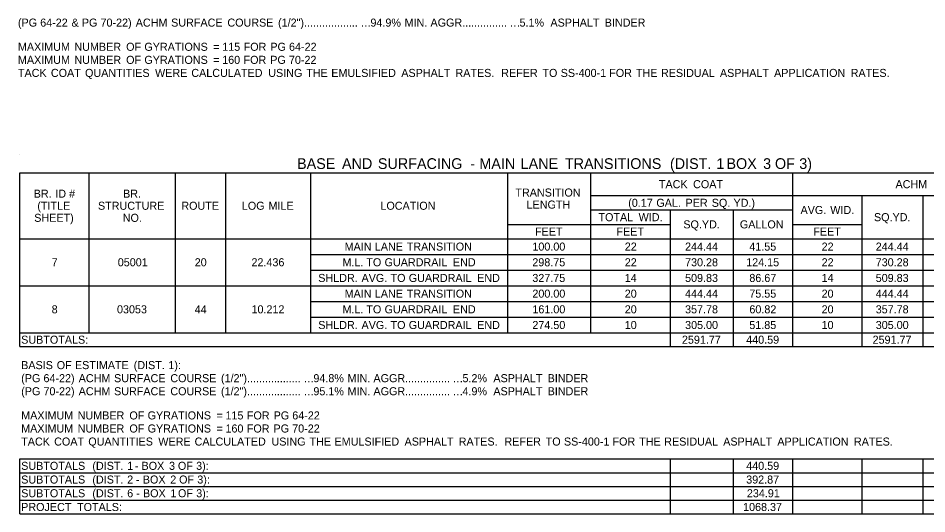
# Model space of a CAD drawing. Extents: x 542596 to 1930787, y -1948294 to 596640.
# Drawn here: x 548347 to 549024, y -1946912 to -1946543 of the extents above; entities that cross this region are included whole.
import ezdxf

# ---------------------------------------------------------------- set-up
doc = ezdxf.new("R2010")
doc.units = 0
doc.layers.add('Default', color=7, linetype='Continuous')

msp = doc.modelspace()

# ---------------------------------------------------------------- linework, layer by layer
at = {"layer": 'Default'}
for p, q in [((548348.01, -1946644.31), (548348.01, -1946644.31)), ((548348.01, -1946657.96), (549205.03, -1946657.96)), ((548348.01, -1946787.64), (548348.01, -1946657.96)), ((548399.68, -1946777.4), (548399.68, -1946657.96)), ((548464.03, -1946777.4), (548464.03, -1946657.96)), ((548501.57, -1946777.4), (548501.57, -1946657.96)), ((548564.95, -1946777.4), (548564.95, -1946657.96)), ((548711.68, -1946777.4), (548711.68, -1946657.96)), ((548773.6, -1946777.4), (548773.6, -1946657.96)), ((548924.23, -1946675.03), (548924.23, -1946657.96)), ((548924.23, -1946787.64), (548924.23, -1946657.96)), ((548773.6, -1946675.03), (549205.03, -1946675.03)), ((548975.91, -1946675.03), (549021.25, -1946675.03)), ((548975.91, -1946787.64), (548975.91, -1946675.03)), ((549021.25, -1946787.64), (549021.25, -1946675.03)), ((548773.6, -1946685.75), (548924.23, -1946685.75)), ((548833.07, -1946787.64), (548833.07, -1946685.75)), ((548879.87, -1946787.64), (548879.87, -1946685.75)), ((548711.68, -1946696.48), (548773.6, -1946696.48)), ((548711.68, -1946696.48), (548833.07, -1946696.48)), ((548833.07, -1946707.2), (548833.07, -1946696.48)), ((548924.23, -1946696.48), (548975.91, -1946696.48)), ((548924.23, -1946707.2), (548924.23, -1946696.48)), ((548975.91, -1946707.2), (548975.91, -1946696.48)), ((548348.01, -1946707.2), (549205.03, -1946707.2)), ((548833.07, -1946707.2), (548924.23, -1946707.2)), ((548924.23, -1946707.2), (549205.03, -1946707.2)), ((548564.95, -1946718.9), (549205.03, -1946718.9)), ((548924.23, -1946742.3), (548924.23, -1946718.9)), ((548975.91, -1946742.3), (548975.91, -1946718.9)), ((549021.25, -1946742.3), (549021.25, -1946718.9)), ((548564.95, -1946730.6), (549085.11, -1946730.6)), ((548564.95, -1946730.6), (549021.25, -1946730.6)), ((549021.25, -1946730.6), (549205.03, -1946730.6)), ((548348.01, -1946742.3), (549205.03, -1946742.3)), ((548711.68, -1946742.3), (548833.07, -1946742.3)), ((548773.6, -1946777.4), (548773.6, -1946742.3)), ((548564.95, -1946754), (549205.03, -1946754)), ((548924.23, -1946787.64), (548924.23, -1946754)), ((548975.91, -1946787.64), (548975.91, -1946754)), ((549021.25, -1946787.64), (549021.25, -1946754)), ((548564.95, -1946765.7), (549205.03, -1946765.7)), ((548564.95, -1946765.7), (549205.03, -1946765.7)), ((548348.01, -1946777.4), (549205.03, -1946777.4)), ((548833.07, -1946787.64), (548833.07, -1946777.4)), ((548348.01, -1946787.64), (549205.03, -1946787.64)), ((548348.01, -1946871.49), (549205.03, -1946871.49)), ((548348.01, -1946871.49), (549205.03, -1946871.49)), ((548348.01, -1946912.44), (548348.01, -1946871.49)), ((548833.07, -1946912.44), (548833.07, -1946871.49)), ((548833.07, -1946912.44), (548833.07, -1946871.49)), ((548879.87, -1946912.44), (548879.87, -1946871.49)), ((548924.23, -1946912.44), (548924.23, -1946871.49)), ((548975.91, -1946912.44), (548975.91, -1946871.49)), ((549021.25, -1946912.44), (549021.25, -1946871.49)), ((548348.01, -1946881.73), (549205.03, -1946881.73)), ((548348.01, -1946891.96), (549205.03, -1946891.96)), ((548348.01, -1946902.2), (549205.03, -1946902.2)), ((548348.01, -1946912.44), (549205.03, -1946912.44))]:
    msp.add_line(p, q, dxfattribs=at)

# ---------------------------------------------------------------- texts
for s, height, p in [('(PG', 6, (548346.56, -1946548.95)), (' 64-22', 6, (548360.93, -1946548.95)), (' &', 6, (548384.25, -1946548.95)), (' PG', 6, (548391.98, -1946548.95)), (' 70-22)', 6, (548405.89, -1946548.95)), (' ACHM', 6, (548432.14, -1946548.95)), (' SURFACE', 6, (548458.52, -1946548.95)), (' COURSE', 6, (548500.47, -1946548.95)), (' (1/2")..................', 6, (548538.22, -1946548.95)), ('…', 6, (548601.92, -1946548.95)), ('94.9%', 6, (548609.32, -1946548.95)), (' MIN.', 6, (548632.56, -1946548.95)), (' AGGR...............', 6, (548651.85, -1946548.95)), ('…', 6, (548713.05, -1946548.95)), ('5.1%', 6, (548720.45, -1946548.95)), ('  ASPHALT', 6, (548739.03, -1946548.95)), (' BINDER', 6, (548781.73, -1946548.95)), ('MAXIMUM', 6, (548346.56, -1946566.99)), (' NUMBER', 6, (548386.44, -1946566.99)), (' OF', 6, (548424.99, -1946566.99)), (' GYRATIONS', 6, (548438.58, -1946566.99)), (' 115', 6, (548496.6, -1946566.99)), (' FOR', 6, (548512.58, -1946566.99)), (' PG', 6, (548532.49, -1946566.99)), (' 64-22', 6, (548546.4, -1946566.99)), (' =', 6, (548489.85, -1946566.99)), ('MAXIMUM', 6, (548346.56, -1946576.74)), (' NUMBER', 6, (548386.44, -1946576.74)), (' OF', 6, (548424.99, -1946576.74)), (' GYRATIONS', 6, (548438.58, -1946576.74)), (' =', 6, (548489.85, -1946576.74)), (' 160', 6, (548496.6, -1946576.74)), (' FOR', 6, (548512.51, -1946576.74)), (' PG', 6, (548532.42, -1946576.74)), (' 70-22', 6, (548546.34, -1946576.74)), ('TACK', 6, (548346.56, -1946586.49)), (' COAT', 6, (548368.9, -1946586.49)), (' QUANTITIES', 6, (548394.35, -1946586.49)), (' WERE', 6, (548446.55, -1946586.49)), (' CALCULATED', 6, (548473.58, -1946586.49)), (' USING', 6, (548530.9, -1946586.49)), (' THE', 6, (548559.25, -1946586.49)), (' EMULSIFIED', 6, (548577.9, -1946586.49)), (' ASPHALT', 6, (548630.09, -1946586.49)), (' RATES.', 6, (548670.46, -1946586.49)), ('  REFER', 6, (548702.34, -1946586.49)), (' TO', 6, (548735.3, -1946586.49)), (' SS-400-1', 6, (548748.89, -1946586.49)), (' FOR', 6, (548785.09, -1946586.49)), (' THE', 6, (548805, -1946586.49)), (' RESIDUAL', 6, (548823.65, -1946586.49)), (' ASPHALT', 6, (548867.61, -1946586.49)), (' APPLICATION', 6, (548907.98, -1946586.49)), (' RATES.', 6, (548965.06, -1946586.49)), ('BASE', 8, (548554.63, -1946655.14)), (' AND', 8, (548585.14, -1946655.14)), (' SURFACING', 8, (548611.91, -1946655.14)), (' MAIN', 8, (548687.53, -1946655.14)), (' LANE', 8, (548718.3, -1946655.14)), (' TRANSITIONS', 8, (548751.28, -1946655.14)), (' (DIST.', 8, (548829.6, -1946655.14)), (' 1', 8, (548864.22, -1946655.14)), (' BOX', 8, (548871.73, -1946655.14)), (' 3', 8, (548899.05, -1946655.14)), (' OF', 8, (548907.88, -1946655.14)), (' 3)', 8, (548925.99, -1946655.14)), (' -', 8, (548680.78, -1946655.14)), ('TACK', 6, (548824.33, -1946669.5)), (' COAT', 6, (548847.6, -1946669.5)), ('ACHM', 6, (549000.7, -1946669.5)), ('TRANSITION', 6, (548717.36, -1946675.72)), ('BR.', 6, (548358.32, -1946676.58)), (' ID', 6, (548372.18, -1946676.58)), (' #', 6, (548382.48, -1946676.58)), ('BR.', 6, (548424.93, -1946676.58)), ('(0.17', 6, (548801.47, -1946683.39)), (' YD.)', 6, (548877.7, -1946683.39)), ('(TITLE', 6, (548361.02, -1946685.58)), ('STRUCTURE', 6, (548406.22, -1946685.58)), ('ROUTE', 6, (548468.34, -1946685.58)), ('LOG', 6, (548513.46, -1946685.58)), (' MILE', 6, (548531.12, -1946685.58)), ('LOCATION', 6, (548616.76, -1946685.58)), ('LENGTH', 6, (548725.73, -1946684.72)), (' GAL.', 6, (548820.2, -1946683.39)), (' PER', 6, (548841.98, -1946683.39)), (' SQ.', 6, (548861.51, -1946683.39)), ('AVG.', 6, (548929.92, -1946688.75)), (' WID.', 6, (548949.85, -1946688.75)), ('SHEET)', 6, (548358.69, -1946694.58)), ('NO.', 6, (548424.7, -1946694.58)), ('TOTAL', 6, (548779.3, -1946694.11)), (' WID.', 6, (548806.99, -1946694.11)), ('SQ.YD.', 6, (548984.66, -1946694.11)), ('SQ.YD.', 6, (548842.55, -1946699.48)), ('GALLON', 6, (548884.69, -1946699.48)), ('FEET', 6, (548732.01, -1946704.84)), ('FEET', 6, (548792.71, -1946704.84)), ('FEET', 6, (548939.44, -1946704.84)), ('MAIN', 6, (548590.08, -1946716.05)), (' LANE', 6, (548610.36, -1946716.05)), (' TRANSITION', 6, (548634.14, -1946716.05)), ('100.00', 6, (548730.03, -1946716.05)), ('22', 6, (548798.9, -1946716.05)), ('244.44', 6, (548843.86, -1946716.05)), ('41.55', 6, (548891.74, -1946716.05)), ('22', 6, (548945.63, -1946716.05)), ('244.44', 6, (548985.97, -1946716.05)), ('7', 6, (548371.71, -1946727.75)), ('05001', 6, (548420.98, -1946727.75)), ('20', 6, (548478.34, -1946727.75)), ('22.436', 6, (548520.64, -1946727.75)), ('M.L.', 6, (548588.47, -1946727.75)), (' TO', 6, (548604.04, -1946727.75)), (' GUARDRAIL', 6, (548617.63, -1946727.75)), (' END', 6, (548668.58, -1946727.75)), ('298.75', 6, (548729.99, -1946727.75)), ('22', 6, (548798.9, -1946727.75)), ('730.28', 6, (548843.84, -1946727.75)), ('124.15', 6, (548889.41, -1946727.75)), ('22', 6, (548945.63, -1946727.75)), ('730.28', 6, (548985.95, -1946727.75)), ('SHLDR.', 6, (548570.43, -1946739.45)), (' AVG.', 6, (548600.45, -1946739.45)), (' TO', 6, (548622.08, -1946739.45)), (' GUARDRAIL', 6, (548635.67, -1946739.45)), (' END', 6, (548686.62, -1946739.45)), ('327.75', 6, (548729.99, -1946739.45)), ('14', 6, (548798.88, -1946739.45)), ('509.83', 6, (548843.85, -1946739.45)), ('86.67', 6, (548891.76, -1946739.45)), ('14', 6, (548945.62, -1946739.45)), ('509.83', 6, (548985.95, -1946739.45)), ('MAIN', 6, (548590.08, -1946751.15)), (' LANE', 6, (548610.36, -1946751.15)), (' TRANSITION', 6, (548634.14, -1946751.15)), ('200.00', 6, (548730.03, -1946751.15)), ('20', 6, (548798.88, -1946751.15)), ('444.44', 6, (548843.86, -1946751.15)), ('75.55', 6, (548891.74, -1946751.15)), ('20', 6, (548945.61, -1946751.15)), ('444.44', 6, (548985.97, -1946751.15)), ('8', 6, (548371.7, -1946762.85)), ('03053', 6, (548420.4, -1946762.85)), ('44', 6, (548478.35, -1946762.85)), ('10.212', 6, (548520.67, -1946762.85)), ('M.L.', 6, (548588.47, -1946762.85)), (' TO', 6, (548604.04, -1946762.85)), (' GUARDRAIL', 6, (548617.63, -1946762.85)), (' END', 6, (548668.58, -1946762.85)), ('161.00', 6, (548730.03, -1946762.85)), ('20', 6, (548798.88, -1946762.85)), ('357.78', 6, (548843.84, -1946762.85)), ('60.82', 6, (548891.79, -1946762.85)), ('20', 6, (548945.61, -1946762.85)), ('357.78', 6, (548985.95, -1946762.85)), ('SHLDR.', 6, (548570.43, -1946774.55)), (' AVG.', 6, (548600.45, -1946774.55)), (' TO', 6, (548622.08, -1946774.55)), (' GUARDRAIL', 6, (548635.67, -1946774.55)), (' END', 6, (548686.62, -1946774.55)), ('274.50', 6, (548730.03, -1946774.55)), ('10', 6, (548798.88, -1946774.55)), ('305.00', 6, (548843.86, -1946774.55)), ('51.85', 6, (548891.74, -1946774.55)), ('10', 6, (548945.61, -1946774.55)), ('305.00', 6, (548985.97, -1946774.55)), ('SUBTOTALS:', 6, (548348.98, -1946785.52)), ('2591.77', 6, (548841.51, -1946785.52)), ('440.59', 6, (548889.43, -1946785.52)), ('2591.77', 6, (548983.62, -1946785.52)), ('BASIS', 6, (548348.98, -1946804.48)), (' OF', 6, (548373.25, -1946804.48)), (' ESTIMATE', 6, (548386.83, -1946804.48)), (' (DIST.', 6, (548430.64, -1946804.48)), (' 1):', 6, (548456.45, -1946804.48)), ('(PG', 6, (548348.98, -1946814.23)), (' 64-22)', 6, (548363.36, -1946814.23)), (' ACHM', 6, (548389.61, -1946814.23)), (' SURFACE', 6, (548415.99, -1946814.23)), (' COURSE', 6, (548457.94, -1946814.23)), (' (1/2")..................', 6, (548495.69, -1946814.23)), ('94.8%', 6, (548566.79, -1946814.23)), (' MIN.', 6, (548590.03, -1946814.23)), (' AGGR...............', 6, (548609.32, -1946814.23)), ('5.2%', 6, (548677.92, -1946814.23)), ('  ASPHALT', 6, (548696.5, -1946814.23)), (' BINDER', 6, (548739.19, -1946814.23)), ('(PG', 6, (548348.98, -1946823.98)), (' 70-22)', 6, (548363.36, -1946823.98)), (' ACHM', 6, (548389.61, -1946823.98)), (' SURFACE', 6, (548415.99, -1946823.98)), (' COURSE', 6, (548457.94, -1946823.98)), (' (1/2")..................', 6, (548495.69, -1946823.98)), ('…', 6, (548559.39, -1946814.23)), ('95.1%', 6, (548566.79, -1946823.98)), (' MIN.', 6, (548590.03, -1946823.98)), (' AGGR...............', 6, (548609.32, -1946823.98)), ('…', 6, (548670.52, -1946814.23)), ('4.9%', 6, (548677.92, -1946823.98)), ('  ASPHALT', 6, (548696.5, -1946823.98)), (' BINDER', 6, (548739.19, -1946823.98)), ('…', 6, (548559.39, -1946823.98)), ('…', 6, (548670.52, -1946823.98)), ('MAXIMUM', 6, (548348.98, -1946842.01)), (' NUMBER', 6, (548388.87, -1946842.01)), (' OF', 6, (548427.42, -1946842.01)), (' GYRATIONS', 6, (548441.01, -1946842.01)), (' =', 6, (548492.28, -1946842.01)), (' 115', 6, (548499.03, -1946842.01)), (' FOR', 6, (548515, -1946842.01)), (' PG', 6, (548534.92, -1946842.01)), (' 64-22', 6, (548548.83, -1946842.01)), ('MAXIMUM', 6, (548348.98, -1946851.76)), (' NUMBER', 6, (548388.87, -1946851.76)), (' OF', 6, (548427.42, -1946851.76)), (' GYRATIONS', 6, (548441.01, -1946851.76)), (' 160', 6, (548499.03, -1946851.76)), (' FOR', 6, (548514.94, -1946851.76)), (' PG', 6, (548534.85, -1946851.76)), (' 70-22', 6, (548548.76, -1946851.76)), (' =', 6, (548492.28, -1946851.76)), ('TACK', 6, (548348.98, -1946861.51)), (' COAT', 6, (548371.33, -1946861.51)), (' QUANTITIES', 6, (548396.78, -1946861.51)), (' WERE', 6, (548448.98, -1946861.51)), (' CALCULATED', 6, (548476.01, -1946861.51)), (' USING', 6, (548533.33, -1946861.51)), (' THE', 6, (548561.68, -1946861.51)), (' EMULSIFIED', 6, (548580.33, -1946861.51)), (' ASPHALT', 6, (548632.52, -1946861.51)), (' RATES.', 6, (548672.89, -1946861.51)), ('  REFER', 6, (548704.77, -1946861.51)), (' TO', 6, (548737.73, -1946861.51)), (' SS-400-1', 6, (548751.32, -1946861.51)), (' FOR', 6, (548787.51, -1946861.51)), (' THE', 6, (548807.43, -1946861.51)), (' RESIDUAL', 6, (548826.08, -1946861.51)), (' ASPHALT', 6, (548870.04, -1946861.51)), (' APPLICATION', 6, (548910.41, -1946861.51)), (' RATES.', 6, (548967.49, -1946861.51)), ('SUBTOTALS', 6, (548348.98, -1946879.61)), (' (DIST.', 6, (548399.81, -1946879.61)), (' 1', 6, (548425.78, -1946879.61)), (' BOX', 6, (548436.46, -1946879.61)), (' 3', 6, (548456.95, -1946879.61)), (' OF', 6, (548463.58, -1946879.61)), (' 3):', 6, (548477.16, -1946879.61)), ('440.59', 6, (548889.43, -1946879.61)), (' -', 6, (548431.41, -1946879.61)), ('SUBTOTALS', 6, (548348.98, -1946889.85)), (' (DIST.', 6, (548399.81, -1946889.85)), (' 2', 6, (548425.78, -1946889.85)), (' BOX', 6, (548437.4, -1946889.85)), (' 2', 6, (548457.89, -1946889.85)), (' OF', 6, (548464.46, -1946889.85)), (' 3):', 6, (548478.04, -1946889.85)), ('392.87', 6, (548889.42, -1946889.85)), (' (DIST.', 6, (548399.81, -1946900.08)), (' -', 6, (548432.34, -1946889.85)), (' 3):', 6, (548477.23, -1946900.08)), ('SUBTOTALS', 6, (548348.98, -1946900.08)), (' 6', 6, (548425.78, -1946900.08)), (' -', 6, (548432.47, -1946900.08)), (' BOX', 6, (548437.53, -1946900.08)), (' 1', 6, (548458.01, -1946900.08)), (' OF', 6, (548463.64, -1946900.08)), ('234.91', 6, (548889.92, -1946900.08)), ('PROJECT', 6, (548348.98, -1946910.32)), (' TOTALS:', 6, (548388.41, -1946910.32)), ('1068.37', 6, (548887.09, -1946910.32))]:
    msp.add_text(s, height=height, dxfattribs=at).set_placement(p)

doc.saveas('drawing.dxf')
